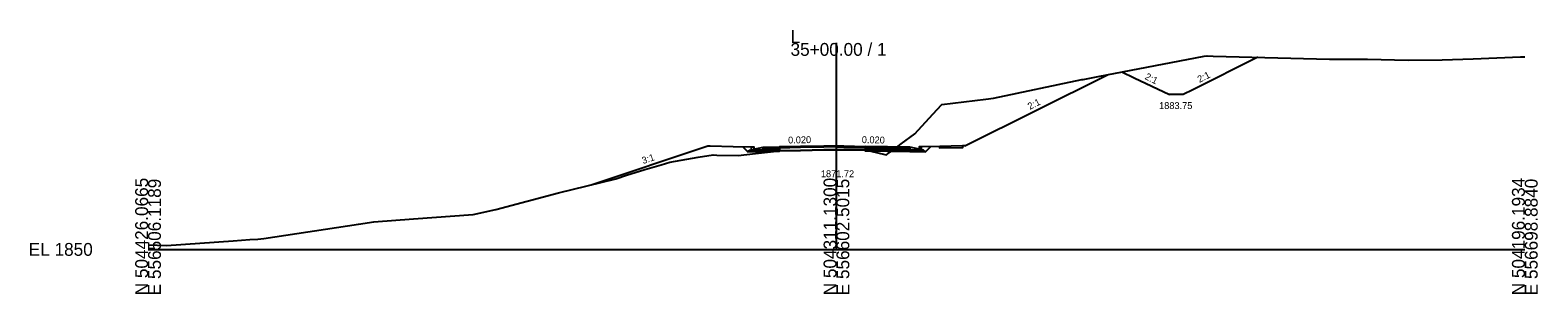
# Model space of a CAD drawing. Extents: x -26 to 4603, y -10 to 4703.
# Drawn here: x 974.3 to 1302.8, y 2440.3 to 2497.8 of the extents above; entities that cross this region are included whole.
import ezdxf

# ---------------------------------------------------------------- set-up
doc = ezdxf.new("R2010")
doc.units = 0
for name, color, linetype in [('Default', 7, 'Continuous'), ('Exist Cross Section Cell', 7, 'Continuous'), ('Exist XS Ground Line', 7, 'Continuous'), ('Prop CMT Pvmt Course 1', 7, 'Continuous'), ('Prop CMT Pvmt Course 2', 7, 'Continuous'), ('Prop CMT Pvmt Course 3', 7, 'Continuous'), ('Prop CMT Pvmt Milling', 7, 'Continuous'), ('Prop CMT Shear Line', 7, 'Continuous'), ('Prop CMT Shld Paved Course 2', 7, 'Continuous'), ('Prop CMT Shld Paved Course 3', 7, 'Continuous'), ('Prop CMT Subgrade Earthwork', 7, 'Continuous'), ('Prop Conc 4in Sidewalk', 7, 'Continuous'), ('Prop Conc Curb and Gutter', 7, 'Continuous'), ('Prop Corridor Mesh Bottom', 7, 'Continuous'), ('Prop XS Ditch Slope Text', 7, 'Continuous'), ('Prop XS Finish Grade', 7, 'Continuous'), ('Prop XS Label Text', 7, 'Continuous'), ('Prop XS SS Elevation Text', 7, 'Continuous'), ('Scratch_Level_9', 7, 'Continuous')]:
    doc.layers.add(name, color=color, linetype=linetype)

msp = doc.modelspace()

# ---------------------------------------------------------------- linework, layer by layer
at = {"layer": 'Exist Cross Section Cell'}
for p, q in [((1150, 2450), (1150, 2495)), ((1000, 2450), (1150, 2450)), ((1150, 2450), (1300, 2450))]:
    msp.add_line(p, q, dxfattribs=at)
at = {"layer": 'Exist XS Ground Line'}
msp.add_lwpolyline([(1000, 2450.99), (1004.03, 2450.82), (1018.52, 2451.86), (1022.21, 2452.14), (1023.89, 2452.22), (1025.26, 2452.38), (1045.84, 2455.53), (1049.18, 2455.98), (1057.81, 2456.64), (1070.86, 2457.58), (1075.75, 2458.7), (1089.47, 2462.35), (1101.95, 2465.39), (1104.25, 2466.17), (1108.22, 2467.39), (1111.8, 2468.43), (1113.69, 2469.02), (1119.87, 2470.1), (1123.15, 2470.59), (1123.95, 2470.54), (1128.58, 2470.44), (1132.34, 2470.9), (1137.56, 2471.48), (1142.17, 2471.59), (1147.23, 2471.72), (1151.58, 2471.71), (1156.25, 2471.72), (1160.58, 2470.69), (1160.88, 2470.61), (1161.09, 2470.76), (1161.5, 2471.08), (1162.84, 2472.08), (1163.07, 2472.25), (1164.1, 2473), (1167.09, 2475.16), (1170.97, 2479.49), (1172.96, 2481.57), (1182.55, 2482.76), (1184.23, 2482.96), (1203.5, 2487.02), (1203.6, 2487.04), (1203.73, 2487.07), (1207.02, 2487.7), (1230.14, 2492.15), (1230.77, 2492.23), (1232.06, 2492.15), (1257.47, 2491.45), (1265.72, 2491.46), (1274.58, 2491.25), (1282.01, 2491.36), (1288.78, 2491.58), (1299.06, 2491.96), (1300, 2491.99)], dxfattribs=at)
at = {"layer": 'Prop CMT Pvmt Course 1'}
for points in [[(1134, 2472.27), (1137.56, 2472.34), (1137.56, 2472.09), (1137.56, 2472.09), (1134, 2472.02), (1134, 2472.02), (1134, 2472.02), (1134, 2472.27), (1134, 2472.27)], [(1147.23, 2472.53), (1147.23, 2472.53), (1142.17, 2472.43), (1142.17, 2472.43), (1137.56, 2472.34), (1137.56, 2471.48), (1137.56, 2471.48), (1142.17, 2471.59), (1142.17, 2471.59), (1147.23, 2471.72), (1147.23, 2471.72), (1147.23, 2471.72), (1150, 2471.72), (1150, 2471.72), (1150, 2472.59), (1147.23, 2472.53), (1147.23, 2472.53)], [(1156.25, 2472.46), (1156.25, 2472.46), (1156.25, 2471.72), (1156.25, 2471.72), (1156.25, 2471.72), (1151.58, 2471.71), (1151.58, 2471.71), (1150, 2471.72), (1150, 2471.72), (1150, 2472.59), (1151.58, 2472.56), (1151.58, 2472.56), (1156.25, 2472.46)], [(1156.25, 2472.46), (1156.25, 2472.46), (1156.25, 2472.21), (1156.25, 2472.21), (1156.25, 2472.21), (1166, 2472.02), (1166, 2472.02), (1166, 2472.27), (1156.25, 2472.46)]]:
    msp.add_lwpolyline(points, dxfattribs=at)
at = {"layer": 'Prop CMT Pvmt Course 2'}
for points in [[(1134, 2472.02), (1137.56, 2472.09), (1137.56, 2471.76), (1137.56, 2471.76), (1134, 2471.68), (1134, 2471.68), (1134, 2471.68), (1134, 2472.02), (1134, 2472.02)], [(1156.25, 2472.21), (1156.25, 2472.21), (1156.25, 2471.88), (1156.25, 2471.88), (1156.25, 2471.88), (1166, 2471.68), (1166, 2471.68), (1166, 2472.02), (1156.25, 2472.21)]]:
    msp.add_lwpolyline(points, dxfattribs=at)
at = {"layer": 'Prop CMT Pvmt Course 3'}
for points in [[(1134, 2471.68), (1137.56, 2471.76), (1137.56, 2471.38), (1137.56, 2471.38), (1134, 2471.31), (1134, 2471.31), (1134, 2471.31), (1134, 2471.68), (1134, 2471.68)], [(1156.25, 2471.88), (1156.25, 2471.88), (1156.25, 2471.5), (1156.25, 2471.5), (1156.25, 2471.5), (1166, 2471.31), (1166, 2471.31), (1166, 2471.68), (1156.25, 2471.88)], [(1169, 2471.62), (1166, 2471.68), (1166, 2471.31), (1166, 2471.31), (1169.38, 2471.24), (1169.38, 2471.24), (1169.38, 2471.24), (1169, 2471.62), (1169, 2471.62)]]:
    msp.add_lwpolyline(points, dxfattribs=at)
at = {"layer": 'Prop CMT Pvmt Milling'}
for points in [[(1150, 2471.72), (1147.23, 2471.72), (1147.23, 2471.72), (1147.23, 2471.72), (1142.17, 2471.59), (1142.17, 2471.59), (1137.56, 2471.48)], [(1150, 2471.72), (1151.58, 2471.71), (1151.58, 2471.71), (1156.25, 2471.72), (1156.25, 2471.72)]]:
    msp.add_lwpolyline(points, dxfattribs=at)
at = {"layer": 'Prop CMT Shld Paved Course 2'}
for points in [[(1147.23, 2472.28), (1147.23, 2472.28), (1142.17, 2472.18), (1142.17, 2472.18), (1137.56, 2472.09), (1137.56, 2471.48), (1137.56, 2471.48), (1142.17, 2471.59), (1142.17, 2471.59), (1147.23, 2471.72), (1147.23, 2471.72), (1147.23, 2471.72), (1150, 2471.72), (1150, 2471.72), (1150, 2472.34), (1147.23, 2472.28), (1147.23, 2472.28)], [(1156.25, 2472.21), (1156.25, 2472.21), (1156.25, 2471.72), (1156.25, 2471.72), (1156.25, 2471.72), (1151.58, 2471.71), (1151.58, 2471.71), (1150, 2471.72), (1150, 2471.72), (1150, 2472.34), (1151.58, 2472.31), (1151.58, 2472.31), (1156.25, 2472.21)]]:
    msp.add_lwpolyline(points, dxfattribs=at)
at = {"layer": 'Prop CMT Shld Paved Course 3'}
msp.add_lwpolyline([(1131, 2471.62), (1134, 2471.68), (1134, 2471.31), (1134, 2471.31), (1130.7, 2471.24), (1130.7, 2471.24), (1130.7, 2471.24), (1131, 2471.62), (1131, 2471.62)], dxfattribs=at)
at = {"layer": 'Prop CMT Subgrade Earthwork'}
for points in [[(1129.54, 2472.41), (1130.7, 2471.24), (1130.7, 2471.24)], [(1130.7, 2471.24), (1130.7, 2471.24), (1137.56, 2471.38)], [(1169.38, 2471.24), (1156.25, 2471.5), (1156.25, 2471.5)], [(1170.55, 2472.41), (1169.38, 2471.24), (1169.38, 2471.24)]]:
    msp.add_lwpolyline(points, dxfattribs=at)
at = {"layer": 'Prop Conc 4in Sidewalk'}
msp.add_lwpolyline([(1172.5, 2472.45), (1172.5, 2472.45), (1172.49, 2472.11), (1172.49, 2472.11), (1172.49, 2472.11), (1177.51, 2472.21), (1177.51, 2472.21), (1177.5, 2472.55), (1172.5, 2472.45)], dxfattribs=at)
at = {"layer": 'Prop Conc Curb and Gutter'}
for points in [[(1132, 2471.87), (1134, 2472.27), (1134, 2471.68), (1134, 2471.68), (1131.5, 2471.63), (1131.5, 2471.63), (1131.5, 2471.63), (1131.5, 2472.37), (1132, 2472.37), (1132, 2472.37), (1132, 2471.87), (1132, 2471.87), (1132, 2471.87)], [(1168, 2471.87), (1166, 2472.27), (1166, 2471.68), (1166, 2471.68), (1168.5, 2471.63), (1168.5, 2471.63), (1168.5, 2471.63), (1168.5, 2472.37), (1168.5, 2472.37), (1168, 2472.37), (1168, 2471.87), (1168, 2471.87), (1168, 2471.87)]]:
    msp.add_lwpolyline(points, dxfattribs=at)
at = {"layer": 'Prop Corridor Mesh Bottom'}
msp.add_lwpolyline([(1166, 2472.27), (1166, 2472.02)], dxfattribs=at)
at = {"layer": 'Prop XS Finish Grade'}
msp.add_line((1122.5, 2472.55), (1127.5, 2472.45), dxfattribs=at)
for points in [[(1241.79, 2491.88), (1227.66, 2484.81), (1225.54, 2483.75)], [(1178, 2472.56), (1209.07, 2488.09)], [(1212.16, 2488.71), (1214.86, 2487.42), (1222.54, 2483.75)], [(1225.54, 2483.75), (1222.54, 2483.75), (1222.54, 2483.75), (1222.54, 2483.75), (1222.54, 2483.75), (1222.54, 2483.75)], [(1096.52, 2464.07), (1122, 2472.56), (1122, 2472.56)], [(1122, 2472.56), (1122.5, 2472.55), (1122.5, 2472.55)], [(1127.5, 2472.45), (1131.5, 2472.37), (1131.5, 2472.37)], [(1172.5, 2472.45), (1168.5, 2472.37), (1168.5, 2472.37)], [(1178, 2472.56), (1177.5, 2472.55), (1177.5, 2472.55)]]:
    msp.add_lwpolyline(points, dxfattribs=at)
at = {"layer": 'Scratch_Level_9'}
msp.add_lwpolyline([(1134, 2472.27), (1134, 2472.02)], dxfattribs=at)

# ---------------------------------------------------------------- texts
at = {"layer": 'Default'}
msp.add_text('-', height=0.0001, dxfattribs=at).set_placement((1000, 2450))
at = {"layer": 'Exist Cross Section Cell'}
for s, p in [('L', (1140, 2495)), ('35+00.00 / 1', (1140, 2492.2)), ('EL 1850', (974, 2448.6))]:
    msp.add_text(s, height=2.8, dxfattribs=at).set_placement(p)
for s, p in [('N 504426.0665', (1000, 2440)), ('E 556506.1189', (1002.8, 2440)), ('N 504311.1300', (1150, 2440)), ('E 556602.5015', (1152.8, 2440)), ('N 504196.1934', (1300, 2440)), ('E 556698.8840', (1302.8, 2440))]:
    msp.add_text(s, height=2.8, rotation=90, dxfattribs=at).set_placement(p)
at = {"layer": 'Prop CMT Shear Line'}
for p in [(1209.07, 2488.09), (1222.54, 2483.75), (1122, 2472.56), (1122.5, 2472.55), (1127.5, 2472.45), (1132, 2471.87), (1134, 2472.27), (1134, 2472.27), (1150, 2472.59), (1166, 2472.27), (1166, 2472.27), (1168, 2471.87), (1172.5, 2472.45), (1177.5, 2472.55), (1178, 2472.56), (1096.52, 2464.06)]:
    msp.add_text('X', height=0.0025, dxfattribs=at).set_placement(p)
at = {"layer": 'Prop XS Ditch Slope Text'}
msp.add_text('1883.75', height=1.5, dxfattribs=at).set_placement((1220.31, 2480.6))
at = {"layer": 'Prop XS Label Text'}
for s, rotation, p in [('2:1', 333.4349, (1217.08, 2487.2)), ('2:1', 26.5651, (1229.11, 2486.3)), ('2:1', 26.5651, (1192.12, 2480.4)), ('0.020', 1.1458, (1139.48, 2473.08)), ('0.020', 358.8542, (1155.51, 2473.18)), ('3:1', 18.4332, (1107.87, 2468.59))]:
    msp.add_text(s, height=1.5, rotation=rotation, dxfattribs=at).set_placement(p)
at = {"layer": 'Prop XS SS Elevation Text'}
msp.add_text('1871.72', height=1.5, dxfattribs=at).set_placement((1146.61, 2465.74))

doc.saveas('drawing.dxf')
